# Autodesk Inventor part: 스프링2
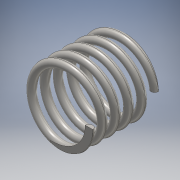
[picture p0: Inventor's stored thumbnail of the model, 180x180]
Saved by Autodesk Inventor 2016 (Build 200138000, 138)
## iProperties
Created: 2019-11
Part Number: 스프링2
Material: 스테인레스 스틸
Document SubType Name: Modeling
Designer: user
Mass: 6.54897 g
Surface Area: 16.6959 cm^2
Volume: 0.818622 cm^3
Density: 8 g/cm^3
Appearance: 반연마
Author: user
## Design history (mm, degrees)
sketch "스케치1"
  geometry: L1 (0, 0)-(8.5, 0); L2 (8.5, 0)-(8.5, 17.5); L3 (8.5, 17.5)-(0, 17.5); L4 (0, 17.5)-(0, 0); C1 r 1 at (8.5, 0)
  constraints: 8 end point, 2 parallel, 1 centre point, 1 coincident, 1 horizontal, 1 perpendicular
  dimensions: "d0" = 17.5 distance between parallel lines of L1 L3 (derived); "d1" = 17 diameter of L2 L4; "d2" = 2 diameter of C1
feature "코일1" sketch "스케치1" pitch "d3" = 10; turns "d5" = 5; dims "d4" = 17.5 (= d0), "d6" = 0, angle "d7" = 90 deg, angle "d8" = 90 deg, "d9" = 0, "d10" = 0
sketch "스케치2"
  geometry: L1 (0, 14.377)-(17.5, 14.377); L2 (17.5, 14.377)-(17.5, -14.377); L3 (17.5, -14.377)-(0, -14.377); L4 (0, -14.377)-(0, 14.377); 2 further points
  constraints: 8 end point, 2 parallel, 1 coincident, 1 horizontal, 1 midpoint, 1 perpendicular
  dimensions: "d11" = 28.75382 distance of L1.end L2.end; "d12" = 17.5 distance between parallel lines of L4 L2 (= d0)
extrude "돌출1" sketch "스케치2" stored distance "d13" = 26.25; taper "d14" = 0 deg
node "솔리드1"
